// Mitsubishi GX Works2 project: MM-17MR-4MTS-F350-H3G-A例程   PLC: FX3G

PROGRAM MAIN
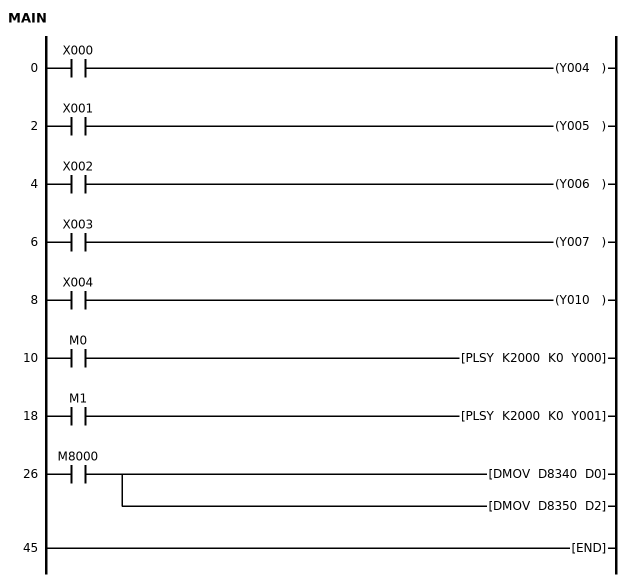
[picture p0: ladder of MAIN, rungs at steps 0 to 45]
0     LD      X000
      OUT     Y004
2     LD      X001
      OUT     Y005
4     LD      X002
      OUT     Y006
6     LD      X003
      OUT     Y007
8     LD      X004
      OUT     Y010
10    LD      M0
      PLSY    K2000 K0 Y000
18    LD      M1
      PLSY    K2000 K0 Y001
26    LD      M8000
      DMOV    D8340 D0
      DMOV    D8350 D2
45    END
END_PROGRAM
